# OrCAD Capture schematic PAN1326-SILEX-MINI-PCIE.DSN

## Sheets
1 PAGE2: size C; title: HHHRP Wireless expansion board; rev: X; company: Freescale Semiconductor; note: SCH-XXXXX PDF: SPF-XXXXX; note: 6501 William Cannon Drive West; note: Austin, TX 78735-8598
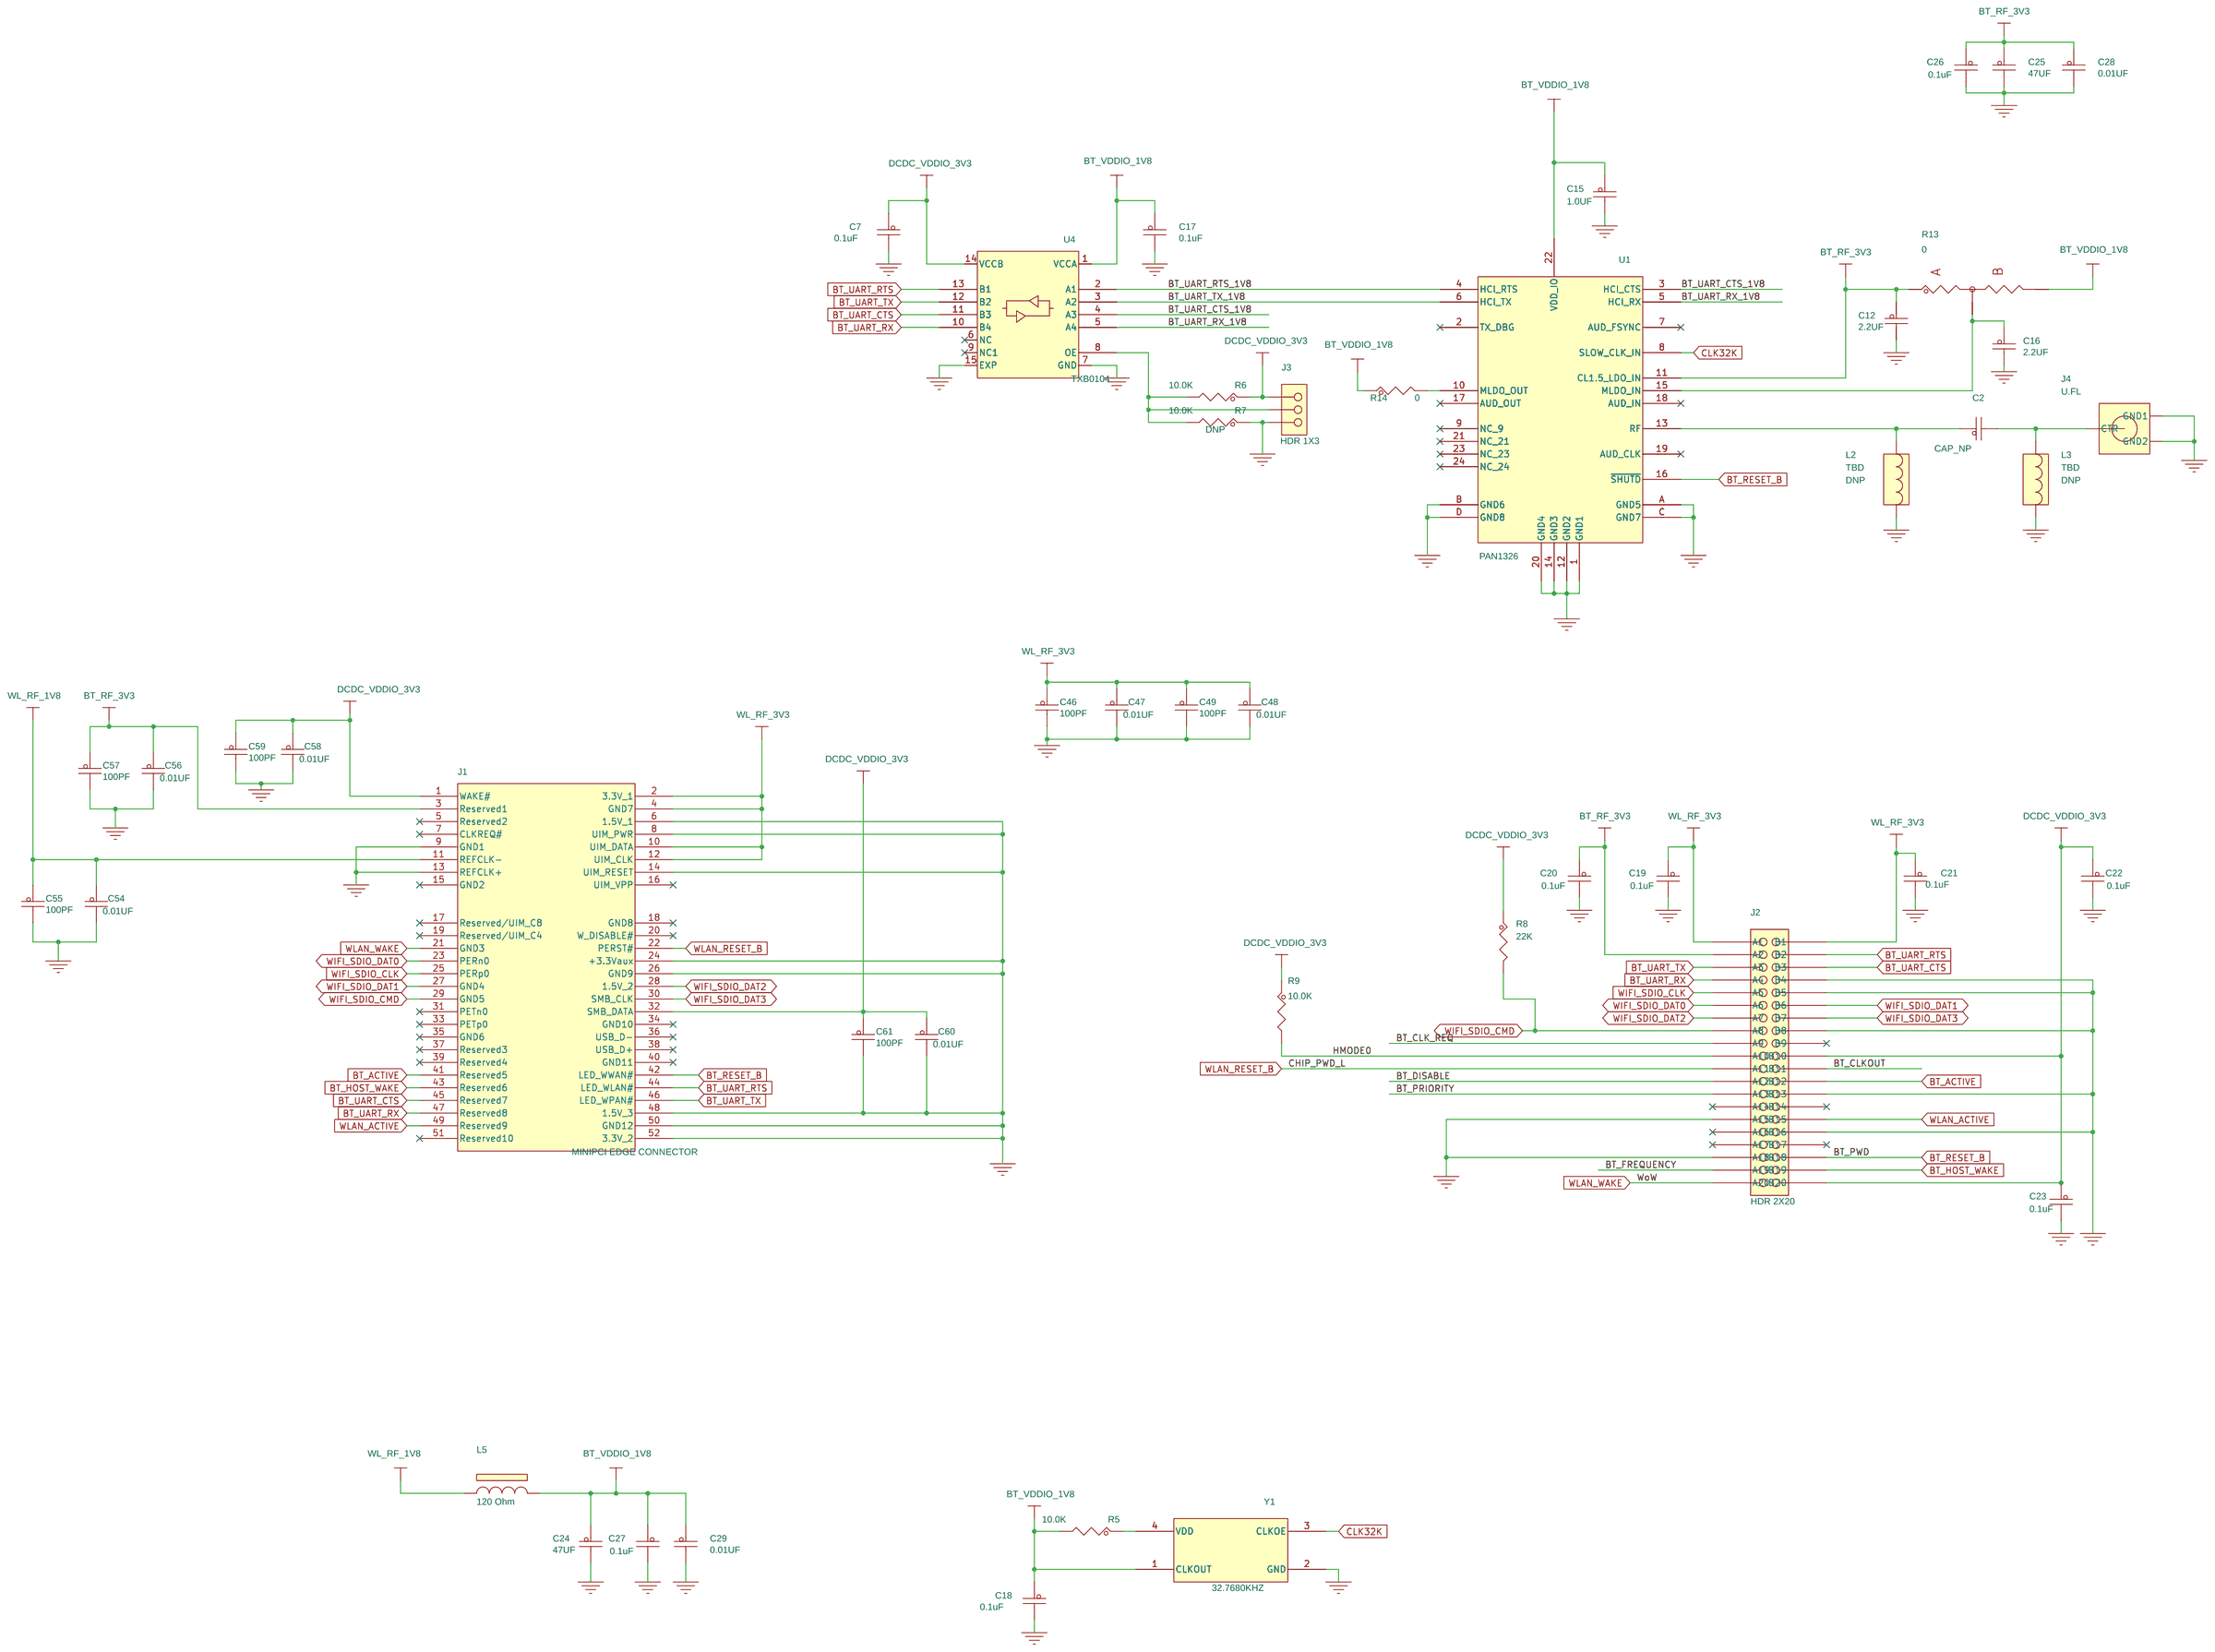
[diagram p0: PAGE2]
2 PAGE1
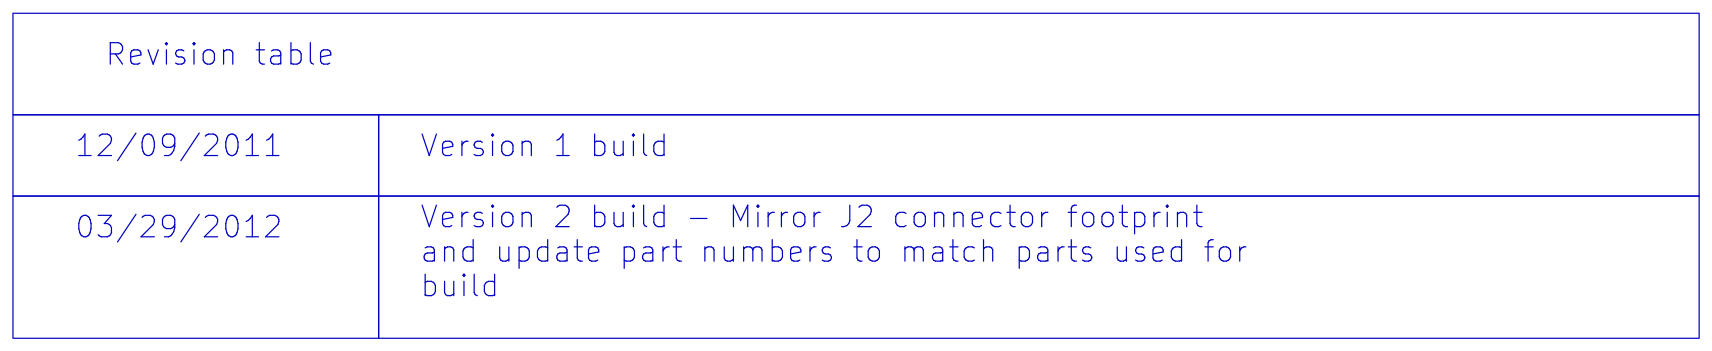
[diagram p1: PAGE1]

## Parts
C2  CAP_NP  [CC0402_25]
C7  0.1uF  [CC0402_25]
C12  2.2UF  [CC0603_OV]
C15  1.0UF  [CC0402_25]
C16  2.2UF  [CC0603_OV]
C17  0.1uF  [CC0402_25]
C18  0.1uF  [CC0402_25]
C19  0.1uF  [CC0402_25]
C20  0.1uF  [CC0402_25]
C21  0.1uF  [CC0402_25]
C22  0.1uF  [CC0402_25]
C23  0.1uF  [CC0402_25]
C24  47UF  [CC1206]
C25  47UF  [CC1206]
C26  0.1uF  [CC0402_25]
C27  0.1uF  [CC0402_25]
C28  0.01UF  [CC0402_25]
C29  0.01UF  [CC0402_25]
C46  100PF  [CC0402_25]
C47  0.01UF  [CC0402_25]
C48  0.01UF  [CC0402_25]
C49  100PF  [CC0402_25]
C54  0.01UF  [CC0402_25]
C55  100PF  [CC0402_25]
C56  0.01UF  [CC0402_25]
C57  100PF  [CC0402_25]
C58  0.01UF  [CC0402_25]
C59  100PF  [CC0402_25]
C60  0.01UF  [CC0402_25]
C61  100PF  [CC0402_25]
J1  MINIPCI EDGE CONNECTOR  [con2x26_mini_pcie_halfsize]
J2  HDR 2X20  [hdr_2x20_0p4_sm]
J3  HDR 1X3  [hdr103_stag_sm]
J4  U.FL  [CON_3_UFL_R_SMT]
L2  TBD  [IND_0402]
L3  TBD  [IND_0402]
L5  120 Ohm  [IND_0402]
R5  10.0K  [RC0402_25]
R6  10.0K  [RC0402_25]
R7  10.0K  [RC0402_25]
R8  22K  [RC0402_25]
R9  10.0K  [RC0402_25]
R13  0  [R603-X2]
R14  0  [RC0603_OV]
U1  PAN1326  [lga24_0p9_9p2x9p7]
U4  TXB0104  [qfn14_rgy]
Y1  32.7680KHZ  [xtlosc4_3p3x1p6_sm]

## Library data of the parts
C2 = CAP_NP: 0R; ASSY_OPT: DNP; CAD_APPROVED: Yes; FPLIST: CC0402_25,CC0402_HD,0402_CC; HEIGHT: 0.55MM; MFG_NAME01: N/A; MFG_PN01: N/A; ROHS: Yes; Tolerance: 0.5PF %
C7 C17-C23 C26 C27 = CAP_NP: CAP CER 0.1UF 16V 10% X5R 0402; AGILE_PN: 150-75663; CAD_APPROVED: Yes; FPLIST: CC0402_25,CC0402_HD,0402_CC; HEIGHT: 0.55MM; MFG_NAME01: TDK; MFG_PN01: C1005X5R1C104K; ROHS: Yes; Tolerance: 10%
C12 C16 = CAP_NP: CAP CER 2.2UF 6.3V 10% X5R 1608; AGILE_PN: 150-30127; CAD_APPROVED: Yes; FPLIST: CC0603_OV,CC0603,CC0603_CC; HEIGHT: 0.9MM; MFG_NAME01: TDK; MFG_PN01: C1608X5R0J225K; ROHS: Yes; Tolerance: 10%
C15 = CAP_NP: CAP CER 1.0UF 6.3V 10% X5R 0402; CAD_APPROVED: Yes; FPLIST: CC0402_25,CC0402_HD,0402_CC; HEIGHT: 0.74MM; MFG_NAME01: TAIYO YUDEN; MFG_PN01: JMK105BJ105KV-F; ROHS: Yes; Tolerance: 5%
C24 C25 = CAP_NP: CAP CER 47UF 6.3V 20% X5R 1206; AGILE_PN: 150-77385; CAD_APPROVED: Yes; HEIGHT: 1.8 MM; MFG_NAME01: TAIYO YUDEN; MFG_PN01: JMK316BJ476ML-T; ROHS: Yes; Tolerance: 20%
C28 C29 C47 C48 C54 C56 C58 C60 = CAP_NP: CAP CER 0.01UF 16V 20% X7R 0402; CAD_APPROVED: Yes; FPLIST: CC0402_25,CC0402_HD,0402_CC; HEIGHT: 0.4MM; MFG_NAME01: TDK; MFG_PN01: C1005X7R1C103M; ROHS: Yes; Tolerance: 20%
C46 C49 C55 C57 C59 C61 = CAP_NP: CAP CER 100PF 50V 5% C0G 0402; CAD_APPROVED: Yes; FPLIST: CC0402_25,CC0402_HD,0402_CC; HEIGHT: 0.55MM; MFG_NAME01: TAIYO YUDEN; MFG_PN01: UMK105CG101JV-F; ROHS: Yes; Tolerance: 5%
J1 = MINI_PCI_LATCH_52P: CON 2x26 MINIPCIE HALF SIZE EDGE FINGER SMT 0.8MM SP -- NO PART TO ORDER; AGILE_PN: 211-79182; CAD_APPROVED: Yes; HEIGHT: 0.1MM; MFG_NAME01: N/A; ROHS: Yes
J2 = CONN_HDR_20X2: HDR 2X20 SKT SMT 0.4MM SP 57H --; AGILE_PN: 211-79190; CAD_APPROVED: Yes; HEIGHT: 1.45MM; MFG_NAME01: KYOCERA; MFG_PN01: 24 5602 040 001 829 H+; ROHS: Yes
J3 = CONN_HDR_3X1: HDR 1X3 SMT 100MIL SP 380H AU; CAD_APPROVED: Yes; HEIGHT: 10.03 MM; MFG_NAME01: SAMTEC; MFG_PN01: TSM-103-01-T-SV; ROHS: Yes
J4 = UFL: CON 1 COAX SKT SMT -- AU; AGILE_PN: 211-30001; CAD_APPROVED: Yes; HEIGHT: 1.25 MM; MFG_NAME01: HIROSE; MFG_PN01: U.FL-R-SMT(01); ROHS: Yes
L2 = BEAD: IND  0402; ASSY_OPT: DNP; CAD_APPROVED: Yes; FPLIST: IND_0402,0402_CC; HEIGHT: 0.45MM; MFG_NAME01: N/A; MFG_PN01: N/A; PART_TYPE: INDUCTOR\0402; ROHS: Yes; Tolerance: 7%
L3 = BEAD: IND 0402; ASSY_OPT: DNP; CAD_APPROVED: Yes; FPLIST: IND_0402,0402_CC; HEIGHT: 0.45MM; MFG_NAME01: N/A; MFG_PN01: N/A; PART_TYPE: INDUCTOR\0402; ROHS: Yes; Tolerance: 7%
L5 = INDUCTOR_FERRITE: IND FER BEAD 120 OHM@100MHZ 0.5A 25% 0402; AGILE_PN: 180-77771; CAD_APPROVED: Yes; FPLIST: IND_0402,0402_CC; HEIGHT: 0.55MM; MFG_NAME01: Murata; MFG_PN01: BLM15AG121SN1D; PART_TYPE: FERRITE\BEAD; ROHS: Yes; Tolerance: 25%
R5 R6 R9 = RES: RES MF 10.0K 1/16W 1% 0402; AGILE_PN: 470-75416; CAD_APPROVED: Yes; FPLIST: RC0402_25,RC0402_HD,0402_CC; MFG_NAME01: VISHAY INTERTECHNOLOGY; MFG_PN01: CRCW040210K0FKED; ROHS: Yes; Tolerance: 1%
R7 = RES: RES MF 10.0K 1/16W 1% 0402; AGILE_PN: 470-75416; ASSY_OPT: DNP; CAD_APPROVED: Yes; FPLIST: RC0402_25,RC0402_HD,0402_CC; MFG_NAME01: VISHAY INTERTECHNOLOGY; MFG_PN01: CRCW040210K0FKED; ROHS: Yes; Tolerance: 1%
R8 = RES: RES MF 22K  1/16W 1% 0402; CAD_APPROVED: Yes; FPLIST: RC0402_25,RC0402_HD,0402_CC; MFG_NAME01: PANASONIC; MFG_PN01: ERJ-2RKF2202X; ROHS: Yes; Tolerance: 1%
R13 = RES_0603_X2: RES MF ZERO OHM 1/10W 1% 0603; CAD_APPROVED: Yes; FPLIST: RC0603_OV,RC0603,R603-X2,0603_CC; MFG_NAME01: PANASONIC; MFG_PN01: ERJ-2RKF2202X; ROHS: Yes; Tolerance: 1%
R14 = RES: RES MF ZERO OHM 1/10W 1% 0603; CAD_APPROVED: Yes; FPLIST: RC0603_OV,RC0603,R603-X2,0603_CC; MFG_NAME01: PANASONIC; MFG_PN01: ERJ-2RKF2202X; ROHS: Yes; Tolerance: 1%
U1 = ENW898_24P: IC BT XCVR RADIO MODULE 1.7-4.8V LGA24; AGILE_PN: 312-80347; CAD_APPROVED: Yes; HEIGHT: 2MM; MFG_NAME01: PANASONIC; MFG_PN01: ENW89823A2JF; ROHS: Yes
U4 = TXB0104: IC VXLTR 4BIT BIDIRECTIONAL 1.2-3.6V/1.65-5.5V QFN14; AGILE_PN: 312-78758; CAD_APPROVED: Yes; HEIGHT: 1MM; MFG_NAME01: TEXAS INSTRUMENTS; MFG_PN01: TXB0104RGYRG4; ROHS: Yes
Y1 = OSC_4P: OSC 32.7680KHZ FIXED 1.2-5.5V SMT; AGILE_PN: 230-77232; CAD_APPROVED: Yes; HEIGHT: 1.0MM; MFG_NAME01: GOLLEDGE ELECTRONICS LTD; MFG_PN01: OV7604C7; ROHS: Yes

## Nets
GND: C7.2 C12.2 C15.2 C16.2 C17.2 C18.2 C19.2 C20.2 C21.2 C22.2 C23.2 C24.2 C25.2 C26.2 C27.2 C28.2 C29.2 C46.2 C47.2 C48.2 C49.2 C54.2 C55.2 C56.2 C57.2 C58.2 C59.2 C60.2 C61.2 J1.6(1.5V_1) J1.8(UIM_PWR) J1.9(GND1) J1.13(REFCLK+) J1.14(UIM_RESET) J1.24(+3.3Vaux) J1.26(GND9) J1.48(1.5V_3) J1.50(GND12) J1.52(3.3V_2) J2.8(B4) J2.10(B5) J2.16(B8) J2.26(B13) J2.29(A15) J2.32(B16) J2.35(A18) J3.3 J4.2(GND1) J4.3(GND2) L2.2 L3.2 R7.1 U1.1(GND1) U1.12(GND2) U1.14(GND3) U1.20(GND4) U1.A(GND5) U1.B(GND6) U1.C(GND7) U1.D(GND8) U4.7(GND) U4.15(EXP) Y1.2(GND)
BT_ACTIVE: J1.41(Reserved5) J2.24(B12)
BT_CLK_REQ: J2.17(A9)
BT_CLKOUT: J2.22(B11)
BT_DISABLE: J2.23(A12)
BT_FREQUENCY: J2.37(A19)
BT_HOST_WAKE: J1.43(Reserved6) J2.38(B19)
BT_PRIORITY: J2.25(A13)
BT_RESET_B: J1.42(LED_WWAN#) J2.36(B18) U1.16(~{SHUTD})
BT_RF_3V3: C12.1 C20.1 C25.1 C26.1 C28.1 C56.1 C57.1 J1.3(Reserved1) J2.3(A2) R13.1 U1.11(CL1.5_LDO_IN)
BT_UART_CTS: J1.45(Reserved7) J2.6(B3) U4.11(B3)
BT_UART_CTS_1V8: U1.3(HCI_CTS) U4.4(A3)
BT_UART_RTS: J1.44(LED_WLAN#) J2.4(B2) U4.13(B1)
BT_UART_RTS_1V8: U1.4(HCI_RTS) U4.2(A1)
BT_UART_RX: J1.47(Reserved8) J2.7(A4) U4.10(B4)
BT_UART_RX_1V8: U1.5(HCI_RX) U4.5(A4)
BT_UART_TX: J1.46(LED_WPAN#) J2.5(A3) U4.12(B2)
BT_UART_TX_1V8: U1.6(HCI_TX) U4.3(A2)
BT_VDDIO_1V8: C15.1 C17.1 C18.1 C24.1 C27.1 C29.1 L5.2 R5.2 R13.3 R14.1 U1.22(VDD_IO) U4.1(VCCA) Y1.1(CLKOUT)
CLK32K: U1.8(SLOW_CLK_IN) Y1.3(CLKOE)
DCDC_VDDIO_3V3: C7.1 C22.1 C23.1 C58.1 C59.1 C60.1 C61.1 J1.1(WAKE#) J1.32(SMB_DATA) J2.20(B10) J2.40(B20) J3.1 R6.1 R8.1 R9.1 U4.14(VCCB)
HMODE0: J2.19(A10) R9.2
WIFI_SDIO_CLK: J1.25(PERp0) J2.9(A5)
WIFI_SDIO_CMD: J1.29(GND5) J2.15(A8) R8.2
WIFI_SDIO_DAT0: J1.23(PERn0) J2.11(A6)
WIFI_SDIO_DAT1: J1.27(GND4) J2.12(B6)
WIFI_SDIO_DAT2: J1.28(1.5V_2) J2.13(A7)
WIFI_SDIO_DAT3: J1.30(SMB_CLK) J2.14(B7)
WL_RF_1V8: C54.1 C55.1 J1.11(REFCLK-) L5.1
WL_RF_3V3: C19.1 C21.1 C46.1 C47.1 C48.1 C49.1 J1.2(3.3V_1) J1.4(GND7) J1.10(UIM_DATA) J1.12(UIM_CLK) J2.1(A1) J2.2(B1)
WLAN_ACTIVE: J1.49(Reserved9) J2.30(B15)
WLAN_RESET_B: J1.22(PERST#) J2.21(A11)
WLAN_WAKE: J1.21(GND3) J2.39(A20)
N16415: R5.1 Y1.4(VDD)
N18192: C2.2 J4.1(CTR) L3.1
N18200: C2.1 L2.1 U1.13(RF)
N28121: J3.2 R6.2 R7.2 U4.8(OE)
N39460: C16.1 R13.2 U1.15(MLDO_IN)
N39860: R14.2 U1.10(MLDO_OUT)

Not connected (* = marked no-connect by the designer): J1 5(Reserved2)* 7(CLKREQ#)* 15(GND2)* 16(UIM_VPP)* 17(Reserved/UIM_C8)* 18(GND8)* 19(Reserved/UIM_C4)* 20(W_DISABLE#)* 31(PETn0)* 33(PETp0)* 34(GND10)* 35(GND6)* 36(USB_D-)* 37(Reserved3)* 38(USB_D+)* 39(Reserved4)* 40(GND11)* 51(Reserved10)*; J2 18(B9)* 27(A14)* 28(B14)* 31(A16)* 33(A17)* 34(B17)*; U1 2(TX_DBG)* 7(AUD_FSYNC)* 9(NC)* 17(AUD_OUT)* 18(AUD_IN)* 19(AUD_CLK)* 21(NC)* 23(NC)* 24(NC)*; U4 6(NC)* 9(NC1)*

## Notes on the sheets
sheet 2
- Revision table
- 12/09/2011
- Version 1 build
- 03/29/2012
- Version 2 build - Mirror J2 connector footprint
  and update part numbers to match parts used for
  build
